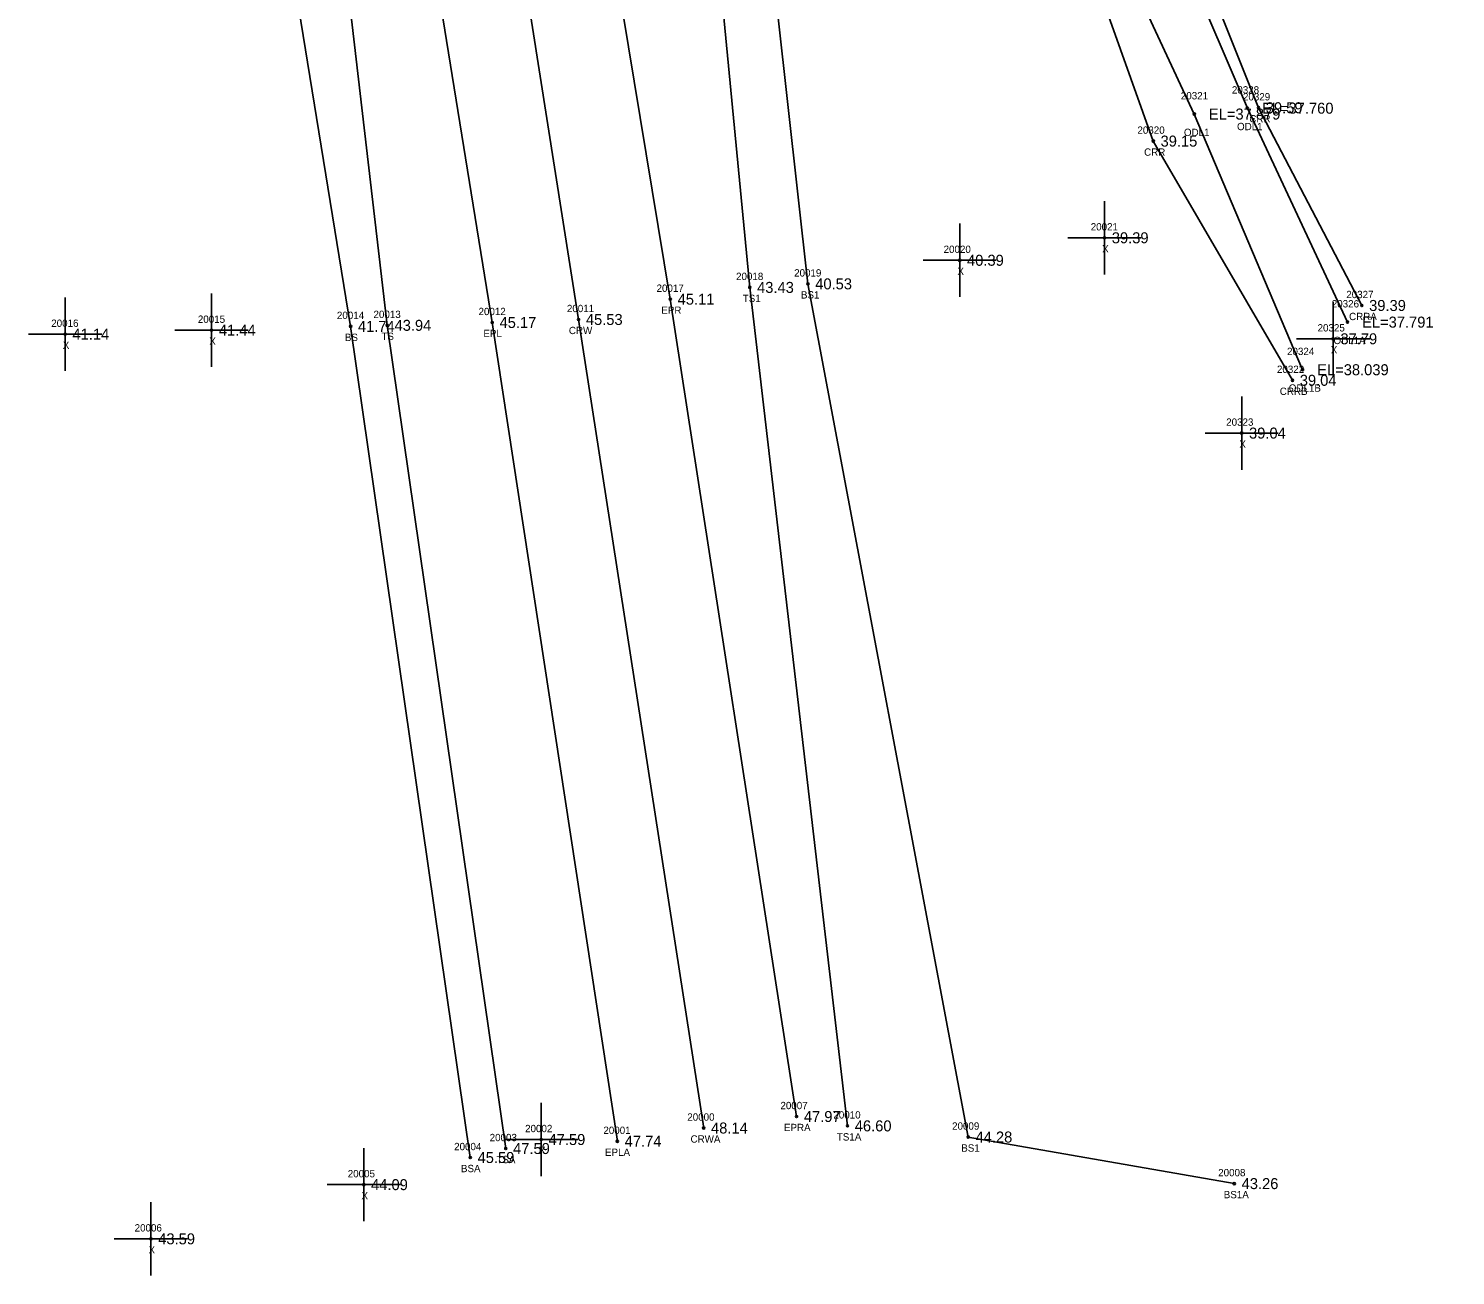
# Model space of a CAD drawing. Extents: x 2619569 to 2620117, y 784503 to 785150.
# Drawn here: x 2619790.9 to 2619985.7, y 784503.2 to 784673.4 of the extents above; entities that cross this region are included whole.
import ezdxf

# ---------------------------------------------------------------- set-up
doc = ezdxf.new("R2010")
doc.units = 0
for name, color, linetype in [('RD_DTM_BkLn1', 7, 'Continuous'), ('RD_DTM_BkLn2', 7, 'Continuous'), ('RD_DTM_BkLn_txCode', 7, 'Continuous'), ('RD_EX_H2O', 7, 'Continuous'), ('RD_EX_H2O_txCode', 7, 'Continuous'), ('RD_EX_Misc', 7, 'Continuous'), ('RD_EX_Misc_txCode', 7, 'Continuous'), ('RD_EX_Road', 7, 'Continuous'), ('RD_EX_Road_txCode', 7, 'Continuous'), ('RD_EX_TX_H2O_ELEV', 7, 'Continuous'), ('RD_EX_TX_Misc_ELEV', 7, 'Continuous'), ('RD_EX_TX_Road_ELEV', 7, 'Continuous'), ('RD_HC_Survey_ELEV', 7, 'Continuous'), ('RD_HC_Survey_txCode', 7, 'Continuous'), ('RD_SMD_Locator', 7, 'Continuous')]:
    doc.layers.add(name, color=color, linetype=linetype)

msp = doc.modelspace()

# ---------------------------------------------------------------- linework, layer by layer
at = {"layer": 'RD_DTM_BkLn1'}
msp.add_lwpolyline([(2619883.08, 784523.28), (2619865.99, 784633.65), (2619850.16, 784734.2), (2619838.88, 784805.4)], dxfattribs=at)
at = {"layer": 'RD_DTM_BkLn2'}
for points in [[(2619856.05, 784520.48), (2619839.86, 784632.85), (2619828.25, 784732.47), (2619822.12, 784782.86), (2619822.87, 784803.9), (2619823.81, 784810.14)], [(2619902.71, 784523.57), (2619889.37, 784638.03), (2619879.63, 784739.19), (2619870.48, 784789.08), (2619861.97, 784802.62)], [(2619955.54, 784515.69), (2619919.2, 784522.05), (2619897.31, 784638.51), (2619886.4, 784736.09), (2619876.43, 784788.17), (2619885.46, 784800.96)], [(2619851.2, 784519.25), (2619834.86, 784632.71), (2619818.82, 784731.21), (2619813.99, 784781.54), (2619816.05, 784799.8)]]:
    msp.add_lwpolyline(points, dxfattribs=at)
at = {"layer": 'RD_EX_H2O'}
for points in [[(2619851.94, 784812.36), (2619867.47, 784809.26), (2619885.8, 784805.06), (2619903.55, 784792.13), (2619903.39, 784761.34), (2619912.7, 784719.27), (2619932.07, 784700.31), (2619950.07, 784661.69), (2619964.86, 784626.79)], [(2619858.79, 784802.44), (2619861.97, 784802.62), (2619885.46, 784800.96), (2619898.93, 784793.37), (2619901.36, 784760.21), (2619910.66, 784718.33), (2619929.66, 784699.53), (2619944.47, 784658), (2619963.48, 784625.35)], [(2619970.99, 784633.29), (2619957.32, 784662.49), (2619943.86, 784693.87), (2619955.27, 784709.18), (2619981.37, 784698.02), (2620005.96, 784721.93), (2620036.75, 784708.95), (2620099.89, 784695.11)], [(2619972.95, 784635.56), (2619958.84, 784662.55), (2619946.5, 784693.39), (2619953.38, 784703.94), (2619980.81, 784695.59), (2620005.48, 784719.58), (2620036.9, 784707.32), (2620099.35, 784692.16)]]:
    msp.add_lwpolyline(points, dxfattribs=at)
at = {"layer": 'RD_EX_Misc'}
for p, q in [((2619937.81, 784639.8), (2619937.81, 784649.8)), ((2619918.04, 784636.73), (2619918.04, 784646.73)), ((2619932.81, 784644.8), (2619942.81, 784644.8)), ((2619913.04, 784641.73), (2619923.04, 784641.73)), ((2619795.88, 784626.64), (2619795.88, 784636.64)), ((2619815.87, 784627.19), (2619815.87, 784637.19)), ((2619969.03, 784626.01), (2619969.03, 784636.01)), ((2619790.88, 784631.64), (2619800.88, 784631.64)), ((2619810.87, 784632.19), (2619820.87, 784632.19)), ((2619964.03, 784631.01), (2619974.03, 784631.01)), ((2619956.55, 784613.14), (2619956.55, 784623.14)), ((2619951.55, 784618.14), (2619961.55, 784618.14)), ((2619860.89, 784516.71), (2619860.89, 784526.71)), ((2619836.66, 784510.55), (2619836.66, 784520.55)), ((2619855.89, 784521.71), (2619865.89, 784521.71)), ((2619831.66, 784515.55), (2619841.66, 784515.55)), ((2619807.59, 784503.15), (2619807.59, 784513.15)), ((2619802.59, 784508.15), (2619812.59, 784508.15))]:
    msp.add_line(p, q, dxfattribs=at)
at = {"layer": 'RD_EX_Road'}
for points in [[(2619895.76, 784524.85), (2619878.52, 784636.42), (2619867.91, 784700.67), (2619864.84, 784718.1), (2619862.04, 784735.87), (2619857.49, 784765.12), (2619856.39, 784772.94), (2619851.61, 784802.52), (2619840.88, 784803.5), (2619838.88, 784805.4), (2619833.01, 784808.5), (2619833.86, 784812.8), (2619837.56, 784814.15), (2619849.59, 784815.47), (2619846.37, 784835.55), (2619834.94, 784832.3), (2619822.88, 784832.99)], [(2619871.29, 784521.47), (2619854.2, 784633.24), (2619837.85, 784734.18), (2619826.43, 784806.91), (2619825.69, 784811.44), (2619822.88, 784832.99)]]:
    msp.add_lwpolyline(points, dxfattribs=at)
at = {"layer": 'RD_SMD_Locator'}
for centre in [(2619957.32, 784662.49), (2619958.84, 784662.55), (2619950.07, 784661.69), (2619944.47, 784658), (2619937.81, 784644.8), (2619918.04, 784641.73), (2619889.37, 784638.03), (2619897.31, 784638.51), (2619878.52, 784636.42), (2619972.95, 784635.56), (2619854.2, 784633.24), (2619865.99, 784633.65), (2619970.99, 784633.29), (2619795.88, 784631.64), (2619815.87, 784632.19), (2619834.86, 784632.71), (2619839.86, 784632.85), (2619969.03, 784631.01), (2619964.86, 784626.79), (2619963.48, 784625.35), (2619956.55, 784618.14), (2619895.76, 784524.85), (2619883.08, 784523.28), (2619902.71, 784523.57), (2619856.05, 784520.48), (2619860.89, 784521.71), (2619871.29, 784521.47), (2619919.2, 784522.05), (2619851.2, 784519.25), (2619836.66, 784515.55), (2619955.54, 784515.69), (2619807.59, 784508.15)]:
    msp.add_circle(centre, 0.15, dxfattribs=at)

# ---------------------------------------------------------------- texts
at = {"layer": 'RD_DTM_BkLn_txCode'}
for s, p in [('20018', (2619887.5, 784639.03)), ('20019', (2619895.43, 784639.51)), ('BS1', (2619896.36, 784636.51)), ('TS1', (2619888.41, 784636.03)), ('20014', (2619832.99, 784633.71)), ('20013', (2619837.99, 784633.85)), ('BS', (2619834.08, 784630.71)), ('TS', (2619839.07, 784630.85)), ('20010', (2619900.79, 784524.57)), ('20003', (2619853.85, 784521.48)), ('TS1A', (2619901.26, 784521.57)), ('20009', (2619917, 784523.05)), ('20004', (2619849, 784520.25)), ('BS1', (2619918.25, 784520.05)), ('TSA', (2619854.76, 784518.48)), ('BSA', (2619849.93, 784517.25)), ('20008', (2619953.34, 784516.69)), ('BS1A', (2619954.1, 784513.69))]:
    msp.add_text(s, height=1, dxfattribs=at).set_placement(p)
at = {"layer": 'RD_EX_H2O_txCode'}
for s, p in [('20321', (2619948.24, 784663.69)), ('20328', (2619955.21, 784664.49)), ('20329', (2619956.72, 784663.55)), ('CRR', (2619957.59, 784660.55)), ('20320', (2619942.31, 784659)), ('ODL1', (2619948.66, 784658.69)), ('ODL1', (2619955.91, 784659.49)), ('CRR', (2619943.22, 784656)), ('20327', (2619970.83, 784636.56)), ('20326', (2619968.85, 784635.29)), ('CRRA', (2619971.21, 784633.56)), ('20324', (2619962.74, 784628.79)), ('ODL1A', (2619969.09, 784630.29)), ('20322', (2619961.36, 784626.35)), ('CRRB', (2619961.75, 784623.35)), ('ODL1B', (2619962.98, 784623.79))]:
    msp.add_text(s, height=1, dxfattribs=at).set_placement(p)
at = {"layer": 'RD_EX_Misc_txCode'}
for s, p in [('20021', (2619935.93, 784645.8)), ('20020', (2619915.84, 784642.73)), ('X', (2619937.49, 784642.8)), ('X', (2619917.73, 784639.73)), ('20016', (2619793.98, 784632.64)), ('20015', (2619814, 784633.19)), ('20325', (2619966.91, 784632.01)), ('X', (2619795.56, 784629.64)), ('X', (2619815.56, 784630.19)), ('X', (2619968.71, 784629.01)), ('20323', (2619954.43, 784619.14)), ('X', (2619956.23, 784616.14)), ('20002', (2619858.69, 784522.71)), ('X', (2619860.58, 784519.71)), ('20005', (2619834.47, 784516.55)), ('X', (2619836.35, 784513.55)), ('20006', (2619805.37, 784509.15)), ('X', (2619807.27, 784506.15))]:
    msp.add_text(s, height=1, dxfattribs=at).set_placement(p)
at = {"layer": 'RD_EX_Road_txCode'}
for s, p in [('20017', (2619876.64, 784637.42)), ('EPR', (2619877.29, 784634.42)), ('20012', (2619852.33, 784634.24)), ('EPL', (2619852.99, 784631.24)), ('20007', (2619893.56, 784525.85)), ('20001', (2619869.38, 784522.47)), ('EPRA', (2619894.04, 784522.85)), ('EPLA', (2619869.6, 784519.47))]:
    msp.add_text(s, height=1, dxfattribs=at).set_placement(p)
at = {"layer": 'RD_EX_TX_H2O_ELEV'}
for s, p in [('EL=37.760', (2619959.32, 784661.74)), ('39.59', (2619959.84, 784661.8)), ('EL=37.879', (2619952.07, 784660.94)), ('39.15', (2619945.47, 784657.25)), ('39.39', (2619973.95, 784634.81)), ('EL=37.791', (2619972.99, 784632.54)), ('EL=38.039', (2619966.86, 784626.04)), ('39.04', (2619964.48, 784624.6))]:
    msp.add_text(s, height=1.5, dxfattribs=at).set_placement(p)
at = {"layer": 'RD_EX_TX_Misc_ELEV'}
for s, p in [('39.39', (2619938.81, 784644.05)), ('40.39', (2619919.04, 784640.98)), ('40.53', (2619898.31, 784637.76)), ('43.43', (2619890.37, 784637.28)), ('41.74', (2619835.86, 784631.96)), ('43.94', (2619840.86, 784632.1)), ('41.14', (2619796.88, 784630.89)), ('41.44', (2619816.87, 784631.44)), ('37.79', (2619970.03, 784630.26)), ('39.04', (2619957.55, 784617.39)), ('46.60', (2619903.71, 784522.82)), ('47.59', (2619861.89, 784520.96)), ('44.28', (2619920.2, 784521.3)), ('47.59', (2619857.05, 784519.73)), ('45.59', (2619852.2, 784518.5)), ('43.26', (2619956.54, 784514.94)), ('44.09', (2619837.66, 784514.8)), ('43.59', (2619808.59, 784507.4))]:
    msp.add_text(s, height=1.5, dxfattribs=at).set_placement(p)
at = {"layer": 'RD_EX_TX_Road_ELEV'}
for s, p in [('45.11', (2619879.52, 784635.67)), ('45.17', (2619855.2, 784632.49)), ('47.97', (2619896.76, 784524.1)), ('47.74', (2619872.29, 784520.72))]:
    msp.add_text(s, height=1.5, dxfattribs=at).set_placement(p)
at = {"layer": 'RD_HC_Survey_ELEV'}
for s, p in [('45.53', (2619866.99, 784632.9)), ('48.14', (2619884.08, 784522.53))]:
    msp.add_text(s, height=1.5, dxfattribs=at).set_placement(p)
at = {"layer": 'RD_HC_Survey_txCode'}
for s, p in [('20011', (2619864.4, 784634.65)), ('CRW', (2619864.67, 784631.65)), ('20000', (2619880.84, 784524.28)), ('CRWA', (2619881.28, 784521.28))]:
    msp.add_text(s, height=1, dxfattribs=at).set_placement(p)

doc.saveas('drawing.dxf')
